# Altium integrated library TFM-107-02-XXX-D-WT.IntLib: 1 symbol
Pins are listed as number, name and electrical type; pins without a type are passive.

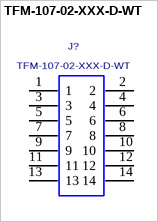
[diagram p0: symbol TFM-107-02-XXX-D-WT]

## TFM-107-02-XXX-D-WT
designator J?
0.050" TERMINAL STRIP, SURFACE MOUNT ASSEMBLY.; MANUFACTURER: SAMTEC
footprint TFM-107-02-XXX-D-WT
pins: 1, 2, 3, 4, 5, 6, 7, 8, 9, 10, 11, 12, 13, 14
